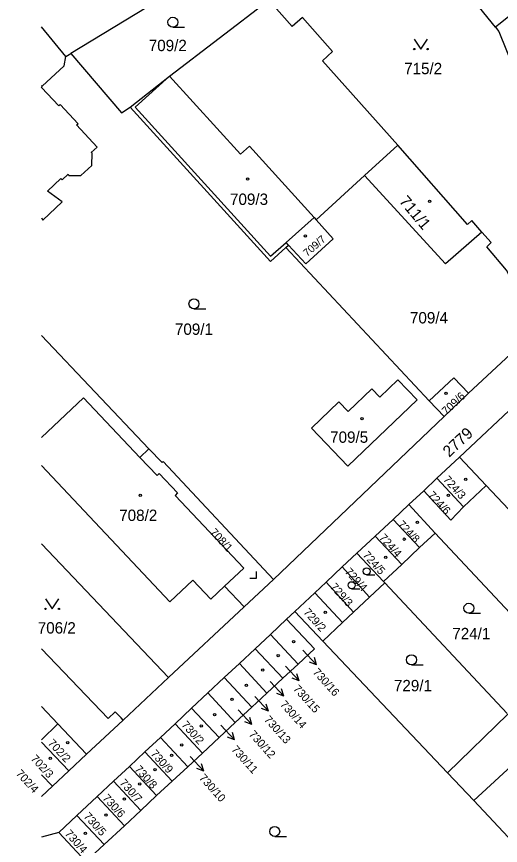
# Model space of a CAD drawing. Extents: x -496682 to -495907, y -1088575 to -1088018.
# Drawn here: x -496677.9 to -496605.6, y -1088281.4 to -1088157.4 of the extents above; entities that cross this region are included whole.
import ezdxf

# ---------------------------------------------------------------- set-up
doc = ezdxf.new("R2010")
doc.units = 0
for name, color, linetype in [('Hranice parcel', 7, 'Continuous'), ('Parcelní čísla', 7, 'Continuous'), ('Pop  PČ popisy', 7, 'Continuous'), ('Vnitřní kresba', 7, 'Continuous'), ('Značky budov', 7, 'Continuous'), ('Značky kultur', 7, 'Continuous')]:
    doc.layers.add(name, color=color, linetype=linetype)

msp = doc.modelspace()

# ---------------------------------------------------------------- linework, layer by layer
at = {"layer": 'Hranice parcel'}
for p, q in [((-496670.53, -1088163.38), (-496674.2, -1088158.91)), ((-496670.53, -1088163.38), (-496669.8, -1088162.94)), ((-496625.88, -1088181.17), (-496620.92, -1088176.62)), ((-496633.12, -1088187.81), (-496625.88, -1088181.17)), ((-496608.33, -1088189.64), (-496609.85, -1088187.91)), ((-496606.96, -1088191.2), (-496608.33, -1088189.64)), ((-496637.64, -1088191.96), (-496637.25, -1088191.6)), ((-496616.2, -1088214.91), (-496637.64, -1088191.96)), ((-496658.12, -1088222.07), (-496674.2, -1088205.13)), ((-496600.11, -1088204.23), (-496610.33, -1088213.73)), ((-496598.99, -1088211.34), (-496611.67, -1088223.3)), ((-496613.98, -1088217.23), (-496610.33, -1088213.73)), ((-496616.2, -1088214.91), (-496613.98, -1088217.23)), ((-496613.98, -1088217.23), (-496639.51, -1088241.62)), ((-496658.12, -1088222.07), (-496659.48, -1088223.35)), ((-496611.67, -1088223.3), (-496615.08, -1088226.47)), ((-496611.67, -1088223.3), (-496607.69, -1088227.55)), ((-496617.01, -1088228.38), (-496615.08, -1088226.47)), ((-496615.08, -1088226.47), (-496611.06, -1088230.75)), ((-496607.69, -1088227.55), (-496611.06, -1088230.75)), ((-496607.69, -1088227.55), (-496589.37, -1088247.15)), ((-496617.01, -1088228.38), (-496619.25, -1088230.42)), ((-496621.61, -1088232.63), (-496619.25, -1088230.42)), ((-496619.25, -1088230.42), (-496615.3, -1088234.67)), ((-496621.61, -1088232.63), (-496624.27, -1088235.13)), ((-496617.64, -1088236.86), (-496621.61, -1088232.63)), ((-496615.3, -1088234.67), (-496617.64, -1088236.86)), ((-496596.95, -1088254.39), (-496615.3, -1088234.67)), ((-496624.27, -1088235.13), (-496627.02, -1088237.7)), ((-496624.27, -1088235.13), (-496620.31, -1088239.36)), ((-496617.64, -1088236.86), (-496620.31, -1088239.36)), ((-496627.02, -1088237.7), (-496629.21, -1088239.75)), ((-496627.02, -1088237.7), (-496623.05, -1088241.94)), ((-496629.21, -1088239.75), (-496631.61, -1088242.01)), ((-496625.14, -1088244.28), (-496629.21, -1088239.75)), ((-496620.31, -1088239.36), (-496623.05, -1088241.94)), ((-496643.86, -1088245.72), (-496639.51, -1088241.62)), ((-496627.51, -1088246.52), (-496631.61, -1088242.01)), ((-496622.86, -1088242.14), (-496625.14, -1088244.28)), ((-496623.05, -1088241.94), (-496622.86, -1088242.14)), ((-496622.86, -1088242.14), (-496604.56, -1088261.65)), ((-496646.82, -1088242.63), (-496643.86, -1088245.72)), ((-496625.14, -1088244.28), (-496627.51, -1088246.52)), ((-496643.86, -1088245.72), (-496655.18, -1088256.3)), ((-496636.3, -1088246.41), (-496637.53, -1088247.57)), ((-496636.3, -1088246.41), (-496632.12, -1088250.83)), ((-496637.53, -1088247.57), (-496639.96, -1088249.83)), ((-496639.96, -1088249.83), (-496642.25, -1088251.98)), ((-496635.82, -1088254.27), (-496639.96, -1088249.83)), ((-496632.12, -1088250.83), (-496613.46, -1088270.55)), ((-496642.25, -1088251.98), (-496644.6, -1088254.18)), ((-496638.12, -1088256.41), (-496642.25, -1088251.98)), ((-496644.6, -1088254.18), (-496646.86, -1088256.3)), ((-496640.47, -1088258.61), (-496644.6, -1088254.18)), ((-496635.82, -1088254.27), (-496638.12, -1088256.41)), ((-496655.18, -1088256.3), (-496661.97, -1088262.66)), ((-496646.86, -1088256.3), (-496649.3, -1088258.59)), ((-496642.74, -1088260.72), (-496646.86, -1088256.3)), ((-496638.12, -1088256.41), (-496640.47, -1088258.61)), ((-496649.3, -1088258.59), (-496651.74, -1088260.88)), ((-496645.23, -1088263.03), (-496649.3, -1088258.59)), ((-496640.47, -1088258.61), (-496642.74, -1088260.72)), ((-496651.74, -1088260.88), (-496654.22, -1088263.2)), ((-496647.64, -1088265.28), (-496651.74, -1088260.88)), ((-496642.74, -1088260.72), (-496645.23, -1088263.03)), ((-496604.44, -1088261.78), (-496613.46, -1088270.55)), ((-496674.2, -1088265.6), (-496671.74, -1088263.22)), ((-496667.44, -1088267.77), (-496671.74, -1088263.22)), ((-496667.44, -1088267.77), (-496661.97, -1088262.66)), ((-496654.22, -1088263.2), (-496656.41, -1088265.25)), ((-496654.22, -1088263.2), (-496650.13, -1088267.6)), ((-496645.23, -1088263.03), (-496647.64, -1088265.28)), ((-496674.2, -1088265.98), (-496670.08, -1088270.24)), ((-496656.41, -1088265.25), (-496658.75, -1088267.43)), ((-496652.33, -1088269.64), (-496656.41, -1088265.25)), ((-496647.64, -1088265.28), (-496650.13, -1088267.6)), ((-496670.08, -1088270.24), (-496667.44, -1088267.77)), ((-496658.75, -1088267.43), (-496661.05, -1088269.59)), ((-496654.67, -1088271.82), (-496658.75, -1088267.43)), ((-496650.13, -1088267.6), (-496652.33, -1088269.64)), ((-496661.05, -1088269.59), (-496663.42, -1088271.81)), ((-496656.97, -1088273.96), (-496661.05, -1088269.59)), ((-496652.33, -1088269.64), (-496654.67, -1088271.82)), ((-496674.2, -1088270.84), (-496672.55, -1088272.55)), ((-496672.55, -1088272.55), (-496670.08, -1088270.24)), ((-496663.42, -1088271.81), (-496665.86, -1088274.1)), ((-496659.35, -1088276.18), (-496663.42, -1088271.81)), ((-496654.67, -1088271.82), (-496656.97, -1088273.96)), ((-496674.2, -1088274.09), (-496672.55, -1088272.55)), ((-496665.86, -1088274.1), (-496668.89, -1088276.94)), ((-496661.8, -1088278.46), (-496665.86, -1088274.1)), ((-496656.97, -1088273.96), (-496659.35, -1088276.18)), ((-496668.89, -1088276.94), (-496671.59, -1088279.46)), ((-496664.84, -1088281.29), (-496668.89, -1088276.94)), ((-496659.35, -1088276.18), (-496661.8, -1088278.46)), ((-496661.8, -1088278.46), (-496664.84, -1088281.29)), ((-496671.59, -1088279.46), (-496674.2, -1088280.16)), ((-496667.54, -1088283.8), (-496671.59, -1088279.46)), ((-496664.84, -1088281.29), (-496667.54, -1088283.8))]:
    msp.add_line(p, q, dxfattribs=at)
for points in [[(-496607.87, -1088116.66), (-496601, -1088111.2), (-496591.02, -1088123.77), (-496593.66, -1088125.97), (-496582.54, -1088140.01), (-496605.81, -1088158.61), (-496606.3, -1088159)], [(-496606.3, -1088159), (-496617.15, -1088145.59), (-496618.65, -1088146.8), (-496619.26, -1088146.37), (-496619.37, -1088146.24), (-496621.25, -1088147.74), (-496621.51, -1088147.95), (-496621.62, -1088147.82), (-496622.15, -1088148.24), (-496627.2, -1088141.89), (-496626.66, -1088141.46), (-496626.77, -1088141.33), (-496626.5, -1088141.12), (-496624.56, -1088139.66), (-496624.44, -1088139.56), (-496628.56, -1088134.37)], [(-496643.14, -1088149.97), (-496647.25, -1088149.22), (-496669.8, -1088162.94)], [(-496660.95, -1088170.93), (-496655.03, -1088166.3), (-496640.19, -1088154.91)], [(-496620.92, -1088176.62), (-496632.18, -1088164.01), (-496630.65, -1088162.63), (-496635.17, -1088157.53), (-496636.71, -1088158.87), (-496640.19, -1088154.91)], [(-496606.3, -1088159), (-496605.78, -1088159.63), (-496603.61, -1088165.05), (-496602.29, -1088166.59)], [(-496669.8, -1088162.94), (-496662.21, -1088171.82), (-496660.95, -1088170.93)], [(-496674.2, -1088187.5), (-496673.99, -1088187.86), (-496671.11, -1088185.12), (-496673.29, -1088183.5), (-496671.29, -1088181.61), (-496671.08, -1088181.82), (-496670.21, -1088181), (-496670.09, -1088181.16), (-496668.29, -1088181.2), (-496666.68, -1088179.68), (-496666.6, -1088177.86), (-496666.74, -1088177.74), (-496665.86, -1088176.92), (-496668.94, -1088173.62), (-496668.73, -1088173.43), (-496671.4, -1088170.57), (-496671.61, -1088170.77), (-496674.19, -1088168.01), (-496674.09, -1088167.82), (-496670.82, -1088164.79), (-496670.53, -1088163.38)], [(-496660.95, -1088170.93), (-496639.93, -1088194.06), (-496637.64, -1088191.96)], [(-496609.85, -1088187.91), (-496610.48, -1088188.52), (-496620.92, -1088176.62)], [(-496608.33, -1088189.64), (-496613.76, -1088194.39), (-496625.88, -1088181.17)], [(-496637.25, -1088191.6), (-496637.61, -1088191.2), (-496633.42, -1088187.48), (-496633.12, -1088187.81)], [(-496637.25, -1088191.6), (-496634.67, -1088194.4), (-496630.55, -1088190.63), (-496633.12, -1088187.81)], [(-496600.11, -1088204.23), (-496601.92, -1088200.52), (-496604.66, -1088195.32), (-496607.61, -1088191.84), (-496606.96, -1088191.2)], [(-496610.33, -1088213.73), (-496612.51, -1088211.45), (-496616.2, -1088214.91)], [(-496624.78, -1088213.12), (-496628.32, -1088216.5), (-496629.71, -1088215.04), (-496633.83, -1088218.99), (-496628.4, -1088224.66), (-496618, -1088214.72), (-496620.89, -1088211.75), (-496623.61, -1088214.35), (-496624.78, -1088213.12)], [(-496659.48, -1088223.35), (-496667.9, -1088214.43), (-496674.2, -1088220.39)], [(-496639.51, -1088241.62), (-496655.99, -1088223.95), (-496656.16, -1088224.12), (-496658.12, -1088222.07)], [(-496659.48, -1088223.35), (-496656.91, -1088226.08), (-496656.58, -1088225.77), (-496653.83, -1088228.68), (-496654.21, -1088229.04), (-496643.95, -1088239.92), (-496646.82, -1088242.63)], [(-496674.2, -1088224.58), (-496654.99, -1088244.96), (-496651.56, -1088241.73), (-496648.88, -1088244.57), (-496646.82, -1088242.63)], [(-496611.06, -1088230.75), (-496612.99, -1088232.74), (-496617.01, -1088228.38)], [(-496674.2, -1088236.29), (-496655.18, -1088256.3)], [(-496631.61, -1088242.01), (-496633.32, -1088243.62), (-496636.3, -1088246.41)], [(-496627.51, -1088246.52), (-496629.16, -1088248.07), (-496632.12, -1088250.83)], [(-496637.53, -1088247.57), (-496633.38, -1088252), (-496635.82, -1088254.27)], [(-496661.97, -1088262.66), (-496662.3, -1088262.31), (-496663.16, -1088261.41), (-496664.23, -1088262.43), (-496674.2, -1088251.99)], [(-496671.74, -1088263.22), (-496674.2, -1088260.62)], [(-496613.46, -1088270.55), (-496609.56, -1088274.67), (-496599.99, -1088284.92)]]:
    msp.add_lwpolyline(points, dxfattribs=at)
at = {"layer": 'Pop  PČ popisy'}
for p, q in [((-496635.11, -1088252.19), (-496633.06, -1088254.39)), ((-496633.06, -1088254.39), (-496633.38, -1088253.31)), ((-496637.72, -1088254.6), (-496635.67, -1088256.79)), ((-496633.06, -1088254.39), (-496634.11, -1088253.99)), ((-496635.67, -1088256.79), (-496635.99, -1088255.72)), ((-496640.02, -1088256.88), (-496637.97, -1088259.07)), ((-496635.67, -1088256.79), (-496636.72, -1088256.4)), ((-496637.97, -1088259.07), (-496638.29, -1088258)), ((-496642.31, -1088259.15), (-496640.26, -1088261.34)), ((-496637.97, -1088259.07), (-496639.02, -1088258.68)), ((-496640.26, -1088261.34), (-496641.31, -1088260.95)), ((-496640.26, -1088261.34), (-496640.58, -1088260.27)), ((-496644.77, -1088261.13), (-496642.72, -1088263.32)), ((-496642.72, -1088263.32), (-496643.04, -1088262.25)), ((-496647.37, -1088263.4), (-496645.32, -1088265.59)), ((-496642.72, -1088263.32), (-496643.77, -1088262.93)), ((-496645.32, -1088265.59), (-496645.64, -1088264.52)), ((-496645.32, -1088265.59), (-496646.37, -1088265.2)), ((-496651.97, -1088268.09), (-496649.92, -1088270.28)), ((-496649.92, -1088270.28), (-496650.24, -1088269.21)), ((-496649.92, -1088270.28), (-496650.97, -1088269.89))]:
    msp.add_line(p, q, dxfattribs=at)
at = {"layer": 'Vnitřní kresba'}
for p, q in [((-496660.17, -1088170.95), (-496655.03, -1088166.3)), ((-496655.03, -1088166.3), (-496644.44, -1088178)), ((-496674.2, -1088167.71), (-496674.09, -1088167.82)), ((-496639.95, -1088193.27), (-496660.17, -1088170.95)), ((-496644.44, -1088178), (-496643.11, -1088176.8)), ((-496643.11, -1088176.8), (-496633.42, -1088187.48)), ((-496639.95, -1088193.27), (-496637.61, -1088191.2)), ((-496633.32, -1088243.62), (-496629.16, -1088248.07)), ((-496609.56, -1088274.67), (-496600.31, -1088266.18))]:
    msp.add_line(p, q, dxfattribs=at)
at = {"layer": 'Značky budov'}
for centre in [(-496643.38, -1088181.72), (-496616.16, -1088185.03), (-496634.73, -1088190.21), (-496613.7, -1088213.76), (-496626.24, -1088217.57), (-496610.74, -1088226.65), (-496659.42, -1088229.03), (-496613.34, -1088229.02), (-496617.98, -1088233.05), (-496619.94, -1088235.59), (-496622.7, -1088238.29), (-496631.75, -1088246.52), (-496636.5, -1088250.92), (-496638.8, -1088253.04), (-496641.1, -1088255.17), (-496643.55, -1088257.44), (-496645.7, -1088259.57), (-496648.3, -1088261.84), (-496650.3, -1088263.54), (-496670.26, -1088266.02), (-496653.21, -1088266.38), (-496672.88, -1088268.4), (-496654.74, -1088267.94), (-496657.2, -1088270.07), (-496659.5, -1088272.2), (-496661.8, -1088274.47), (-496664.56, -1088276.88), (-496667.62, -1088279.58)]:
    msp.add_circle(centre, 0.175, dxfattribs=at)
at = {"layer": 'Značky kultur'}
for p, q in [((-496654.54, -1088159), (-496652.79, -1088159)), ((-496651.39, -1088201.13), (-496649.64, -1088201.13)), ((-496642.03, -1088241.45), (-496642.03, -1088240.45)), ((-496625.57, -1088240.93), (-496624.34, -1088240.93)), ((-496643.03, -1088241.45), (-496642.03, -1088241.45)), ((-496627.82, -1088243.01), (-496626.59, -1088243.01)), ((-496610.27, -1088246.68), (-496608.52, -1088246.68)), ((-496618.86, -1088254.4), (-496617.11, -1088254.4)), ((-496639.32, -1088280.07), (-496637.57, -1088280.07))]:
    msp.add_line(p, q, dxfattribs=at)
for points in [[(-496618.45, -1088160.77), (-496617.45, -1088162.27), (-496616.45, -1088160.77)], [(-496673.59, -1088244.53), (-496672.59, -1088246.03), (-496671.59, -1088244.53)]]:
    msp.add_lwpolyline(points, dxfattribs=at)
for centre, radius in [((-496654.54, -1088158.25), 0.75), ((-496618.45, -1088162.27), 0.1), ((-496616.45, -1088162.27), 0.1), ((-496651.39, -1088200.38), 0.75), ((-496625.57, -1088240.4), 0.525), ((-496627.82, -1088242.48), 0.525), ((-496673.59, -1088246.03), 0.1), ((-496671.59, -1088246.03), 0.1), ((-496610.27, -1088245.93), 0.75), ((-496618.86, -1088253.65), 0.75), ((-496639.32, -1088279.32), 0.75)]:
    msp.add_circle(centre, radius, dxfattribs=at)

# ---------------------------------------------------------------- texts
at = {"layer": 'Parcelní čísla'}
for s, p in [('709/2', (-496658.15, -1088162.57)), ('715/2', (-496619.96, -1088166.02)), ('709/3', (-496646, -1088185.58)), ('709/4', (-496619.09, -1088203.31)), ('709/1', (-496654.24, -1088205.02)), ('709/5', (-496631.03, -1088221.17)), ('708/2', (-496662.57, -1088232.87)), ('706/2', (-496674.75, -1088249.71)), ('724/1', (-496612.76, -1088250.56)), ('729/1', (-496621.49, -1088258.35))]:
    msp.add_text(s, height=1.7, dxfattribs=at).set_placement(p)
for s, height, rotation, p in [('711/1', 1.7, 310, (-496620.8, -1088185.09)), ('709/7', 1.139, 41, (-496634.45, -1088193.39)), ('709/6', 1.2, 43, (-496613.65, -1088217.08)), ('2779', 1.7, 43, (-496613.22, -1088223.41)), ('724/3', 1.2, 312, (-496614.2, -1088226.74)), ('724/6', 1.199, 313, (-496616.5, -1088229.09)), ('724/8', 1.139, 314, (-496620.97, -1088233.47)), ('708/1', 1.2, 313, (-496649.09, -1088234.65)), ('724/4', 1.2, 312, (-496623.78, -1088235.44)), ('724/5', 1.2, 312, (-496626.24, -1088238.04)), ('729/4', 1.2, 312, (-496628.92, -1088240.53)), ('729/3', 1.2, 312, (-496631.1, -1088242.81)), ('729/2', 1.2, 312, (-496635.1, -1088246.58)), ('730/16', 1.2, 312, (-496633.7, -1088255.56)), ('730/15', 1.2, 312, (-496636.63, -1088258.05)), ('730/14', 1.2, 312, (-496638.6, -1088260.39)), ('730/13', 1.2, 312, (-496640.98, -1088262.66)), ('730/2', 1.2, 312, (-496653.35, -1088263.44)), ('730/12', 1.2, 312, (-496643.27, -1088264.86)), ('702/2', 1.2, 313, (-496673.32, -1088266.18)), ('730/9', 1.2, 312, (-496657.96, -1088267.76)), ('730/11', 1.2, 312, (-496645.88, -1088267.13)), ('702/3', 1.2, 313, (-496675.89, -1088268.51)), ('730/8', 1.2, 312, (-496660.35, -1088270.08)), ('702/4', 1.2, 313, (-496678.11, -1088270.75)), ('730/10', 1.2, 312, (-496650.71, -1088271.38)), ('730/7', 1.2, 312, (-496662.61, -1088272.13)), ('730/6', 1.2, 312, (-496665.14, -1088274.4)), ('730/5', 1.2, 312, (-496667.96, -1088277.12)), ('730/4', 1.2, 312, (-496670.79, -1088279.72))]:
    msp.add_text(s, height=height, rotation=rotation, dxfattribs=at).set_placement(p)

doc.saveas('drawing.dxf')
